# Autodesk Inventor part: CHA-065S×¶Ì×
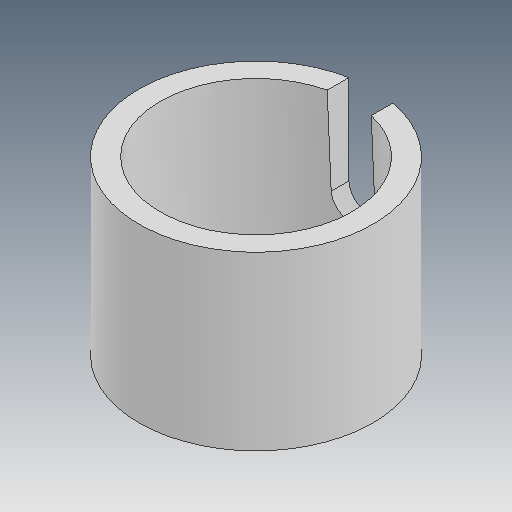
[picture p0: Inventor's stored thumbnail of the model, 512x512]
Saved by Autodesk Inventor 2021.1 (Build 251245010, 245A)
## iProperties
Created: 2019-05
Part Number: CHA-065S×¶Ì×
Material: Ogólny
Document SubType Name: Modeling
Designer: user
Density: 1 g/cm^3
Appearance: Domyślna
Author: user
Revision Number: ÈÎºÎ
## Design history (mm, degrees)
feature "ÊäÈë1"
node "Bryła1"
